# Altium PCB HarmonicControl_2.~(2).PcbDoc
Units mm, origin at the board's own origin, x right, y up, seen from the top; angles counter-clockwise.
Board outline 152.4 x 101.6 mm, 2 copper layers (Top Layer, Bottom Layer); 18 components, 24 nets, 77 pads, 0 vias.
Unrouted connection lines stored in the file: 31.
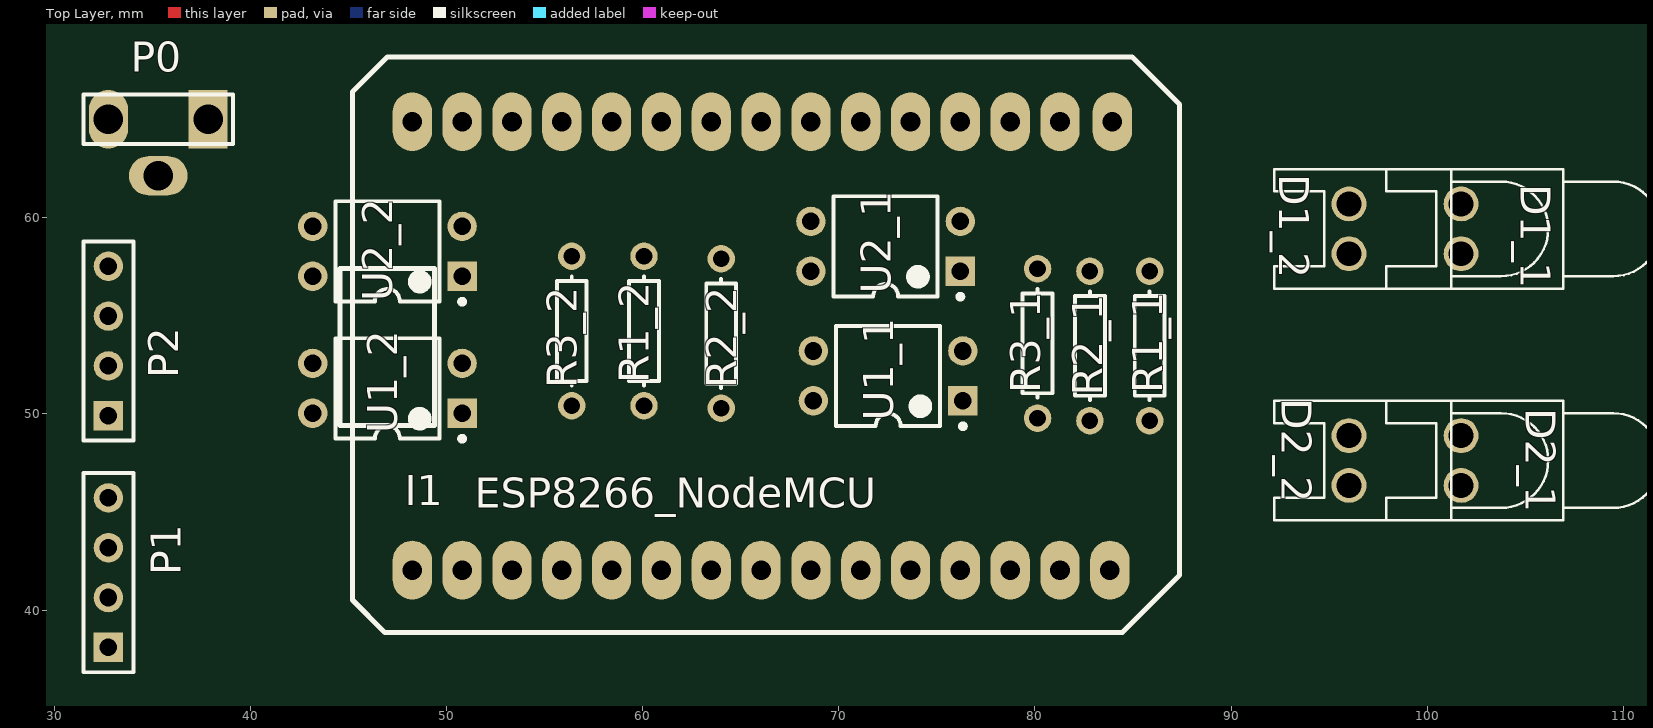
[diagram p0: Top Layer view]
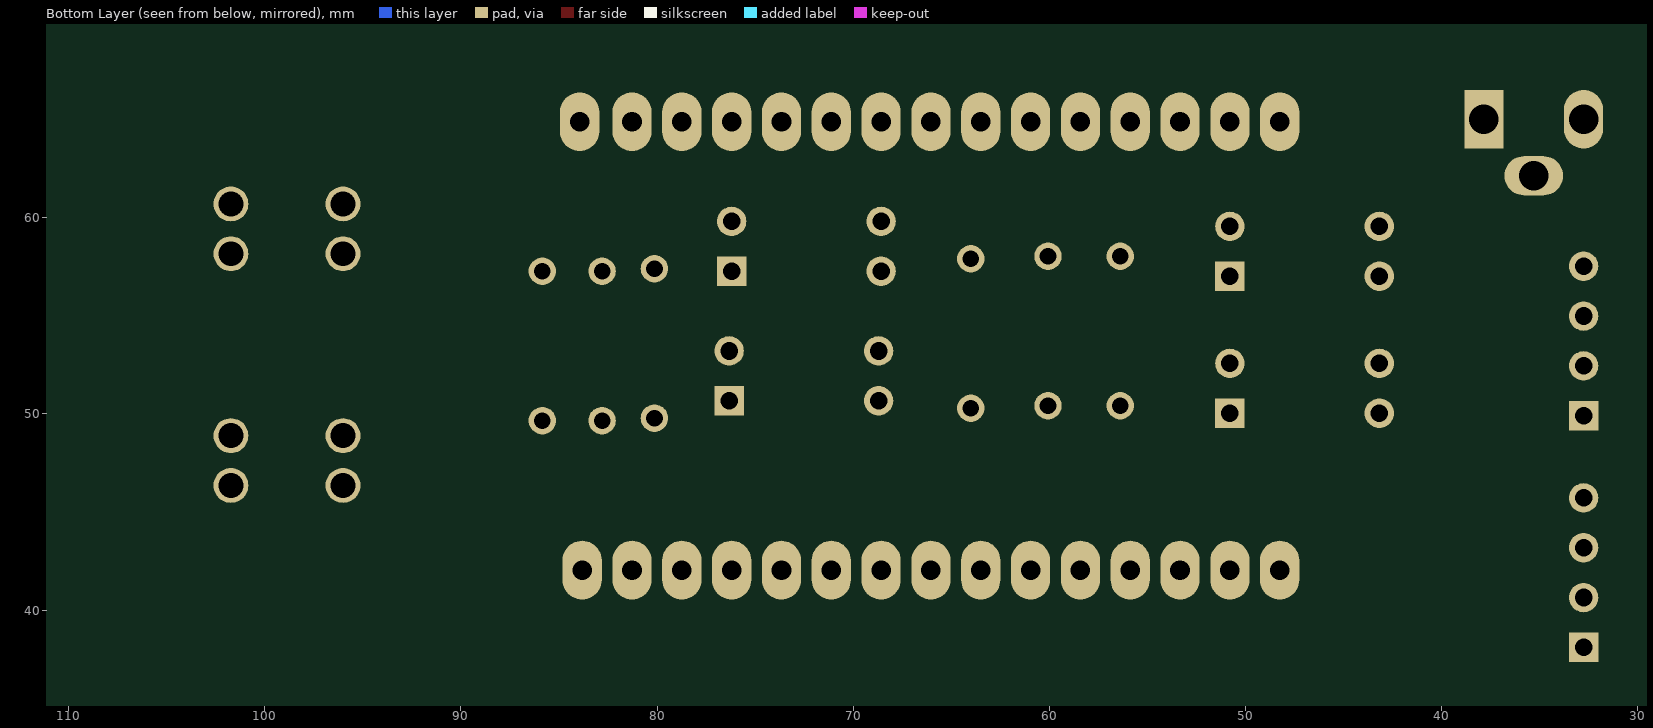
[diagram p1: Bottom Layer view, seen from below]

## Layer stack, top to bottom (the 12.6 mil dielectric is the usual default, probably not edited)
Top Solder: solder mask 0.0102, Solder Resist, Dk 3.5
Top Layer: signal copper 0.0356
Dielectric 1: dielectric 0.32, FR-4, Dk 4.8
Bottom Layer: signal copper 0.0356
Bottom Solder: solder mask 0.0102, Solder Resist, Dk 3.5

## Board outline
25.4,25.4 177.8,25.4 177.8,127 25.4,127

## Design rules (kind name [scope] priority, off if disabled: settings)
Clearance [All] p1: gap=0.254 ignorepadtopadclearanceinfootprint=FALSE except(0: Arc-Hole Track-Hole SMDPad-Hole THPad-Hole Via-Hole Fill-Hole Poly-Hole Region-Hole Text-Hole)
PolygonConnect [All] p1: connectstyle=Relief reliefconductorwidth=0.254 reliefentries=4 polygonreliefangle="90 Angle" airgapwidth=0.254
RoutingVias [All] p1: holewidth=0.711 width=1.27 viastyle="Through Hole" minholewidth=0.711 minwidth=1.27 maxholewidth=0.711 maxwidth=1.27
SolderMaskExpansion [All] p1: expansion=0.102
Width [All] p1: maxlimit=1 minlimit=0.5 preferedwidth=0.8
30 further rules are at their usual default settings.

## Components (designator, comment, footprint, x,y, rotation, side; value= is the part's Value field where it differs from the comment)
D1_1 "LED0" LED-0 101.727,59.436 r90 top
D1_2 "LED0" LED-0 96.012,59.436 r90 top
D2_1 "LED0" LED-0 101.727,47.625 r90 top
D2_2 "LED0" LED-0 96.012,47.625 r90 top
I1 "ESP8266" ESP8266_Node_MCU_V3 48.26,64.897 r270 top
P0 "Jack3.5mm" HDR1X3 37.846,65.024 r180 top
P1 "Cable" HDR1X4 32.766,38.1 r90 top
P2 "Cable" HDR1X4 32.766,49.911 r90 top
R1_1 "Res1" AXIAL-0.3 85.852,53.467 r90 top value=1K
R1_2 "Res1" AXIAL-0.3 60.071,54.229 r90 top value=1K
R2_1 "Res1" AXIAL-0.3 82.804,53.467 r90 top value=1K
R2_2 "Res1" AXIAL-0.3 64.008,54.102 r90 top value=1K
R3_1 "Res1" AXIAL-0.3 80.137,53.594 r90 top value=1K
R3_2 "Res1" AXIAL-0.3 56.388,54.229 r90 top value=1K
U1_1 "InputSignal" DIP-4 72.517,51.943 r180 top
U1_2 "InputSignal" DIP-4 46.99,51.308 r180 top
U2_1 "Output_Control" DIP-4 72.39,58.547 r180 top
U2_2 "Output_Control" DIP-4 46.99,58.293 r180 top

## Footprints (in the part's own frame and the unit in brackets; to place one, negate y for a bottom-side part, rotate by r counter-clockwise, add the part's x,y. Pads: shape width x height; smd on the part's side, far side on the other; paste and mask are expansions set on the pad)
AXIAL-0.3 [mm] "Axial Device, Thru-Hole; 2 Leads; 0.3 in Pin Spacing"
  round 1.4 hole 0.85: 1(-3.81,0) 2(3.81,0)
  silkscreen extent -2.77,-0.76 2.77,0.76
DIP-4 [mm] "DIP; 4 Leads; Row Spacing 7.62 mm; Pitch 2.54 mm"
  rect 1.5x1.5 hole 0.9: 1(-3.81,1.27)
  round 1.5 hole 0.9: 2(-3.81,-1.27) 3(3.81,-1.27) 4(3.81,1.27)
  silkscreen extent -3.94,-2.55 2.65,2.69, body extent -3.15,-2.5 3.15,2.5, height 5.6
ESP8266_Node_MCU_V3 [mm]
  oval 3x2 hole 1 paste+0 mask+0.102: 1(22.86,35.56) 2(22.86,33.02) 3(22.86,30.48) 4(22.86,27.94) 5(22.86,25.4) 6(22.86,22.86) 7(22.86,20.32) 8(22.86,17.78) 9(22.86,15.24) 10(22.86,12.7) 11(22.86,10.16) 12(22.86,7.62) 13(22.86,5.08) 14(22.86,2.54) 15(22.86,0) 16(0,0) 17(0,2.54) 18(0,5.08) 19(0,7.62) 20(0,10.16) 21(0,12.7) 22(0,15.24) 23(0,17.78) 24(0,20.32) 25(0,22.86) 26(0,25.4) 27(0,27.94) 28(0,30.48) 29(0,33.02) 30(0,35.687)
  silkscreen extent -3.3,-3.68 26.04,39.12
HDR1X3 [mm] "Connector; Header; 3 Position"
  rect 2x3 hole 1.5: 1(0,0)
  oval 3x2 hole 1.5: 2(2.54,2.881)
  oval 2x3 hole 1.5: 3(5.08,0)
  silkscreen extent -1.27,-1.27 6.35,1.27
HDR1X4 [mm] "Connector; Header; 4 Position"
  rect 1.5x1.5 hole 0.9: 1(0,0)
  round 1.5 hole 0.9: 2(2.54,0) 3(5.08,0) 4(7.62,0)
  silkscreen extent -1.27,-1.27 8.89,1.27
LED-0 [mil] "LED; 2 Leads"
  round 70 hole 50: 1(50,0) 2(-50,0)
  silkscreen extent -120,-400 120,150

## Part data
D1_1 D1_2 D2_1 D2_2: "Typical INFRARED GaAs LED"
I1: library part ESP8266_Node_MCU_V3
P0: library part "Header 3", "Header, 3-Pin"
P1 P2: library part "Header 4", "Header, 4-Pin"
R1_1 R1_2 R2_1 R2_2 R3_1 R3_2: "Resistor"
U1_1 U1_2 U2_1 U2_2: library part Optoisolator1, "4-Pin Phototransistor Optocoupler"

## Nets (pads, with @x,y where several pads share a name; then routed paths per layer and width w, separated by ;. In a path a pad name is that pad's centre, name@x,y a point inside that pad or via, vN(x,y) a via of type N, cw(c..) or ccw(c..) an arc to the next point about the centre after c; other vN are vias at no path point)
GND: D1_1.2 D1_2.2 I1.17 P0.2 P0.3
NetD1_1_1: D1_1.1 R2_1.2
NetD1_2_1: D1_2.1 R2_2.2
NetD2_1_1: D2_1.1 R3_1.1
NetD2_1_2: D2_1.2 D2_2.2 I1.14
NetD2_2_1: D2_2.1 R3_2.1
NetI1_1: I1.1 R2_1.1 U1_1.3
NetI1_2: I1.2 U2_1.1
NetI1_3: I1.3 R2_2.1 U1_2.3
NetI1_4: I1.4 U2_2.1
NetI1_16: I1.16 P0.1
NetI1_20: I1.20 U1_1.4 U1_2.4
NetP1_1: P1.1 U1_1.1
NetP1_2: P1.2 R1_1.1
NetP1_3: P1.3 U2_1.4
NetP1_4: P1.4 U2_1.3
NetP2_1: P2.1 U1_2.1
NetP2_2: P2.2 R1_2.1
NetP2_3: P2.3 U2_2.4
NetP2_4: P2.4 U2_2.3
NetR1_1_2: R1_1.2 U1_1.2
NetR1_2_2: R1_2.2 U1_2.2
NetR3_1_2: R3_1.2 U2_1.2
NetR3_2_2: R3_2.2 U2_2.2
pads on no net: I1.5 I1.6 I1.7 I1.8 I1.9 I1.10 I1.11 I1.12 I1.13 I1.15 I1.18 I1.19 I1.21 I1.22 I1.23 I1.24 I1.25 I1.26 I1.27 I1.28 I1.29 I1.30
